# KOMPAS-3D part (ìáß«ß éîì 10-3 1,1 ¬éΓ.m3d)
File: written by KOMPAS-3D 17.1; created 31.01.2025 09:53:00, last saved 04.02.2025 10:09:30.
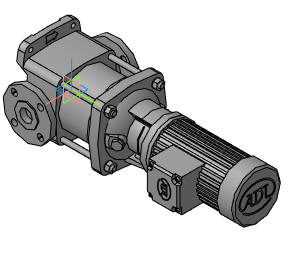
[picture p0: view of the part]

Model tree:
1. Операция без истории:3  (labels: Насос ВМН 10-3 1,1 кВт)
